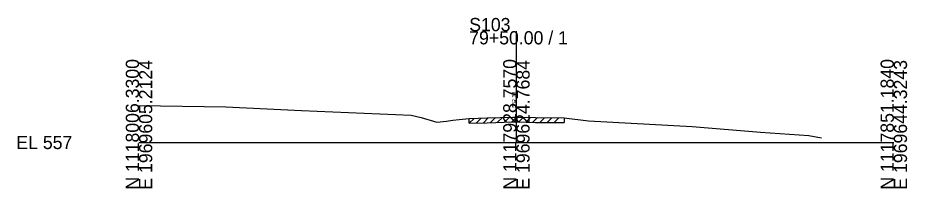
# Model space of a CAD drawing. Extents: x -26 to 163, y -10 to 45020.
# Drawn here: x -25.7 to 162.8, y 38490.3 to 38526.4 of the extents above; entities that cross this region are included whole.
import ezdxf

# ---------------------------------------------------------------- set-up
doc = ezdxf.new("R2010")
doc.units = 0
for name, color, linetype in [('RD_GPK_XS_Cell', 7, 'Continuous'), ('RD_XS_ExGround', 7, 'Continuous'), ('RD_XS_ExPaveRet', 7, 'Continuous'), ('RD_XS_TX_Elev_EX', 7, 'Continuous')]:
    doc.layers.add(name, color=color, linetype=linetype)

msp = doc.modelspace()

# ---------------------------------------------------------------- linework, layer by layer
at = {"layer": 'RD_GPK_XS_Cell'}
for p, q in [((80, 38500), (80, 38523.59)), ((0, 38500), (80, 38500)), ((80, 38500), (160, 38500))]:
    msp.add_line(p, q, dxfattribs=at)
at = {"layer": 'RD_XS_ExGround'}
for p, q in [((0, 38507.86), (18.39, 38507.54)), ((18.39, 38507.54), (34.45, 38506.81)), ((34.45, 38506.81), (57.7, 38505.82)), ((57.7, 38505.82), (59.84, 38505.28)), ((59.84, 38505.28), (63.16, 38504.29)), ((63.16, 38504.29), (65.21, 38504.5)), ((65.21, 38504.5), (66.53, 38504.76)), ((66.53, 38504.76), (67.89, 38504.88)), ((67.89, 38504.88), (70, 38505.06)), ((70, 38505.06), (73.83, 38505.19)), ((73.83, 38505.19), (79.22, 38505.4)), ((79.22, 38505.4), (80, 38505.38)), ((80, 38505.38), (84.04, 38505.26)), ((84.04, 38505.26), (90.14, 38505.2)), ((90.14, 38505.2), (95.26, 38504.61)), ((95.26, 38504.61), (117.27, 38503.37)), ((117.27, 38503.37), (131.73, 38502.19)), ((131.73, 38502.19), (142.02, 38501.46)), ((142.02, 38501.46), (144.65, 38500.97))]:
    msp.add_line(p, q, dxfattribs=at)
at = {"layer": 'RD_XS_ExPaveRet'}
for p, q in [((70, 38504.06), (71.04, 38505.09)), ((70, 38504.06), (70, 38505.06)), ((70, 38504.06), (73.83, 38504.19)), ((71.5, 38504.11), (72.54, 38505.15)), ((73, 38504.16), (74.04, 38505.2)), ((73.83, 38504.19), (79.22, 38504.4)), ((74.5, 38504.22), (75.54, 38505.26)), ((76, 38504.28), (77.04, 38505.32)), ((77.5, 38504.34), (78.54, 38505.38)), ((79, 38504.39), (79.99, 38505.38)), ((79.22, 38504.4), (80, 38504.38)), ((80, 38504.38), (84.04, 38504.26)), ((80.5, 38504.37), (81.47, 38505.34)), ((82, 38504.32), (82.97, 38505.3)), ((83.5, 38504.28), (84.48, 38505.26)), ((84.04, 38504.26), (90.14, 38504.2)), ((85, 38504.25), (85.99, 38505.24)), ((86.5, 38504.24), (87.49, 38505.23)), ((88, 38504.22), (88.99, 38505.21)), ((90.14, 38505.2), (90.14, 38504.2))]:
    msp.add_line(p, q, dxfattribs=at)

# ---------------------------------------------------------------- texts
at = {"layer": 'RD_GPK_XS_Cell'}
for s, p in [('S103', (70, 38523.59)), ('79+50.00 / 1', (70, 38520.79)), ('EL 557', (-26, 38498.6))]:
    msp.add_text(s, height=2.8, dxfattribs=at).set_placement(p)
for s, p in [('N 1118006.3300', (0, 38490)), ('E 1969605.2124', (2.8, 38490)), ('N 1117928.7570', (80, 38490)), ('E 1969624.7684', (82.8, 38490)), ('N 1117851.1840', (160, 38490)), ('E 1969644.3243', (162.8, 38490))]:
    msp.add_text(s, height=2.8, rotation=90, dxfattribs=at).set_placement(p)
at = {"layer": 'RD_XS_TX_Elev_EX'}
msp.add_text('562.38', height=0.8, rotation=90, dxfattribs=at).set_placement((79.9, 38507.38))

doc.saveas('drawing.dxf')
